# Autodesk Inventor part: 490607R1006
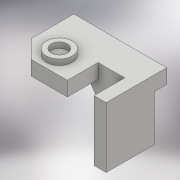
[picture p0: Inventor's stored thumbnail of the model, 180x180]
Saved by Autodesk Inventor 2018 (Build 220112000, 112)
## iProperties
Created: 2019-06
Part Number: 490607R1006
Material: 일반
Document SubType Name: Modeling
Designer: 6507_12
Density: 1 g/cm^3
Appearance: 기본값
Author: 6507_12
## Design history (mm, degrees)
sketch "스케치2"
  geometry: L1 (57.5, 98.884)-(-57.5, 98.884); L2 (-57.5, 98.884)-(-57.5, 45.884); L3 (57.5, 23.884)-(57.5, 98.884); L4 (57.5, 98.884)-(-57.5, 23.884); L5 (-57.5, 98.884)-(57.5, 23.884); L6 (-57.5, 98.884)-(-57.5, 45.884); L7 (-57.5, 45.884)-(-35.5, 23.884); L8 (57.5, 23.884)-(42.5, 23.884); L9 (42.5, 23.884)-(42.5, 61.884); L10 (42.5, 61.884)-(57.5, 61.884); L11 (-35.5, 23.884)-(9.5, 23.884); L12 (9.5, 23.884)-(9.5, 61.884); L13 (9.5, 61.884)-(42.5, 61.884); L14 (-35.5, 23.884)-(9.5, 23.884); L15 (42.5, 23.884)-(57.5, 23.884); L16 (57.5, 61.884)-(57.5, 83.884); L17 (57.5, 83.884)-(32.5, 83.884); L18 (32.5, 83.884)-(32.5, 61.884); L19 (32.5, 83.884)-(-5.68, 83.884); L20 (-5.68, 83.884)-(-5.68, 61.884); L21 (-5.68, 61.884)-(32.5, 61.884); 2 further points
  constraints: 42 end point, 5 perpendicular, 3 parallel, 3 point on line, 2 horizontal, 2 midpoint, 1 collinear, 1 vertical
  dimensions: "d0" = 115 distance of L1.start L1.end; "d1" = 75 distance of L3.start L1.start; "d3" = 53 distance of L2.end L1.end; "d5" = 15 distance of L3.start L8.end; "d11" = 22 distance of L10.end L16.end; "d14" = 25 distance of L16.end L17.end; "d15" = 90 deg angle of L17 L16
extrude "돌출1" new body sketch "스케치2" distance "d16" = 75; taper "d17" = 0 deg
sketch "스케치8"
  geometry: L1 (-5.68, 61.884)-(42.5, 61.884) reference; L2 (57.5, 83.884)-(-5.68, 83.884) reference; L3 (-5.68, 83.884)-(-5.68, 61.884) reference; L4 (57.5, 98.884)-(-57.5, 98.884) reference; L5 (57.5, 23.884)-(57.5, 98.884) reference; L6 (9.5, 23.884)-(9.5, 61.884) reference; L7 (-35.5, 23.884)-(9.5, 23.884) reference; L8 (-57.5, 45.884)-(-35.5, 23.884) reference; L9 (-57.5, 98.884)-(-57.5, 45.884) reference; 1 further point
extrude "돌출2" join sketch "스케치8" distance "d18" = 18; taper "d19" = 0 deg
sketch "스케치9"
  geometry: L1 (-35.5, 23.884)-(-57.5, 45.884) reference; C1 r 16 at (-22.5, 45.884); C2 r 10 at (-22.5, 45.884); 1 further point
  constraints: 2 centre point, 1 coincident
extrude "돌출3" join sketch "스케치9" distance "d23" = 7; taper "d24" = 0 deg
sketch "스케치10"
  geometry: L1 (28.5, 45.884)-(28.5, 73.884); L2 (28.5, 73.884)-(16.5, 73.884); L3 (16.5, 73.884)-(16.5, 45.884); C1 r 16 at (22.5, 45.884) reference; C2 r 6 at (22.5, 73.884); A1 r 6 centre (22.5, 45.884) between (28.5, 45.884) and (16.5, 45.884); 1 further point
  constraints: 6 end point, 2 centre point, 2 perpendicular, 2 point on circle, 1 coincident, 1 midpoint, 1 tangent, 1 vertical
  dimensions: "d25" = 12 diameter of A1; "d26" = 28 distance of L1.start L1.end; "d27" = 12 diameter of C2
extrude "돌출4" cut sketch "스케치10" distance "d28" = 7; taper "d29" = 0 deg
sketch "스케치14"
  geometry: L1 (0, -57)-(63.18, -57) reference; L2 (63.18, 0)-(0, 0) reference; L3 (0, 0)-(0, -57) reference; L4 (48.18, 0)-(63.18, 0) reference; L5 (63.18, 0)-(38.18, 0); L6 (0, 0)-(48.18, 0) reference; L7 (15.18, -57)-(0, -57) reference; L8 (38.18, 0)-(0, -57); L9 (0, -57)-(63.18, -57); 1 further point
  constraints: 6 end point, 1 collinear, 1 point on line
  dimensions: "d30" = 25 distance of L2.start L5.end
extrude "돌출5" cut sketch "스케치14" extent not by distance; stored distance "d31" = 7; taper "d32" = 0 deg
node "솔리드1"
